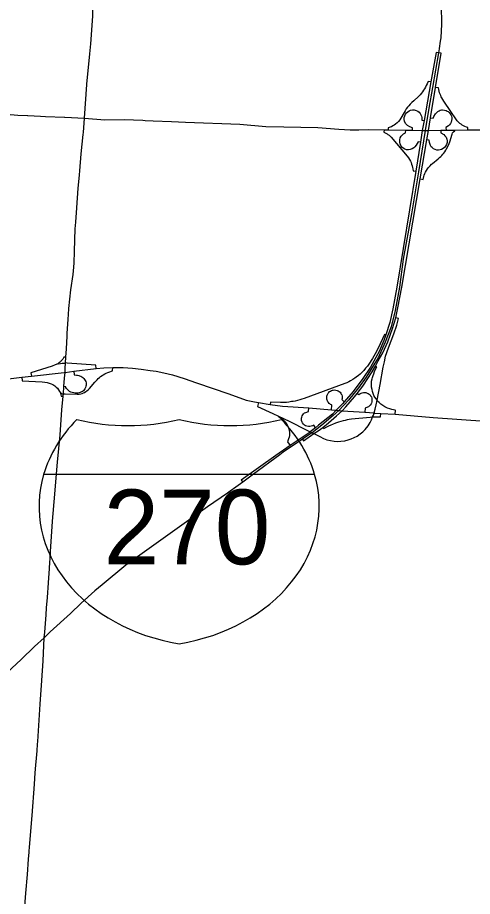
# Model space of a CAD drawing. Extents: x -7.1 to 34, y 0 to 22.
# Drawn here: x 7.196 to 7.759, y 16.034 to 17.122 of the extents above; entities that cross this region are included whole.
import ezdxf

# ---------------------------------------------------------------- set-up
doc = ezdxf.new("R2010")
doc.units = 0
for name, color, linetype in [('GM_X_Interchange_Ramps', 7, 'Continuous'), ('GM_X_Interstate_Route', 7, 'Continuous'), ('GM_X_Interstate_Shield', 7, 'Continuous'), ('GM_X_State_Route', 7, 'Continuous'), ('GM_X_US_Route', 7, 'Continuous')]:
    doc.layers.add(name, color=color, linetype=linetype)

msp = doc.modelspace()

# ---------------------------------------------------------------- linework, layer by layer
at = {"layer": 'GM_X_Interchange_Ramps'}
for points in [[(7.7167, 17.0785), (7.7138, 17.079), (7.7074, 17.0426), (7.699, 16.9948), (7.6968, 16.9823), (7.6944, 16.9677), (7.6886, 16.9318), (7.6653, 16.7884), (7.6603, 16.7615), (7.6566, 16.7446), (7.6515, 16.729), (7.6492, 16.7223), (7.6433, 16.7084), (7.6325, 16.6893), (7.6233, 16.675), (7.6111, 16.6589), (7.6002, 16.646), (7.5986, 16.6441), (7.5903, 16.6358), (7.5856, 16.631), (7.5684, 16.6171), (7.5646, 16.6141), (7.5581, 16.6089), (7.5579, 16.6088), (7.5333, 16.592), (7.5153, 16.5798), (7.4725, 16.5493), (7.4745, 16.5465)], [(7.5485, 16.5999), (7.5498, 16.598), (7.5625, 16.6068), (7.5678, 16.6104), (7.5737, 16.6145), (7.5808, 16.6202), (7.5906, 16.6287), (7.5974, 16.6352), (7.6023, 16.64), (7.6127, 16.6522), (7.6162, 16.6567), (7.6231, 16.6654), (7.6347, 16.6834), (7.6387, 16.6905), (7.6423, 16.697), (7.6478, 16.7069), (7.654, 16.7205), (7.6599, 16.7369), (7.6639, 16.7503), (7.6664, 16.7627), (7.6714, 16.7883), (7.6943, 16.9223), (7.7026, 16.9707), (7.7046, 16.9823), (7.7046, 16.9824), (7.7071, 16.9979), (7.7133, 17.0356), (7.7202, 17.078), (7.7167, 17.0785)], [(7.7074, 17.0426), (7.7041, 17.0431), (7.7028, 17.0401), (7.7018, 17.0379), (7.7007, 17.0359), (7.6997, 17.034), (7.6985, 17.0322), (7.6971, 17.0302), (7.6957, 17.0284), (7.6942, 17.0265), (7.6933, 17.0255), (7.6919, 17.0242), (7.6865, 17.0192), (7.684, 17.0169), (7.6819, 17.0149), (7.68, 17.0128), (7.6785, 17.011), (7.677, 17.0089), (7.6756, 17.0067), (7.6743, 17.0047), (7.6702, 16.9974), (7.6689, 16.9954), (7.6675, 16.9935), (7.6658, 16.9917), (7.6637, 16.9899), (7.662, 16.9887), (7.6605, 16.9879), (7.6588, 16.987), (7.6569, 16.9863), (7.6545, 16.9856), (7.6545, 16.983)], [(7.7534, 16.983), (7.7533, 16.986), (7.7514, 16.9865), (7.7496, 16.9872), (7.7479, 16.988), (7.7463, 16.9889), (7.7448, 16.9899), (7.7434, 16.991), (7.742, 16.9922), (7.7409, 16.9933), (7.74, 16.9944), (7.7234, 17.0188), (7.7221, 17.0207), (7.721, 17.0226), (7.7203, 17.024), (7.7196, 17.0255), (7.7189, 17.0272), (7.7183, 17.029), (7.7177, 17.031), (7.7169, 17.035), (7.7133, 17.0356)], [(7.6847, 16.9825), (7.6848, 16.9855), (7.6814, 16.9868), (7.6785, 16.9884), (7.676, 16.9911), (7.6749, 16.9937), (7.6745, 16.996), (7.6745, 16.9982), (7.6751, 17.0006), (7.6759, 17.0023), (7.6773, 17.0042), (7.6787, 17.0055), (7.6805, 17.0066), (7.6823, 17.0073), (7.6845, 17.0077), (7.6868, 17.0077), (7.6894, 17.007), (7.6911, 17.0061), (7.6928, 17.0048), (7.6942, 17.0032), (7.6952, 17.0016), (7.6958, 16.9999), (7.6961, 16.9984), (7.6964, 16.9952), (7.699, 16.9948)], [(7.7071, 16.9979), (7.7104, 16.9974), (7.7113, 16.9997), (7.7131, 17.003), (7.7142, 17.0043), (7.716, 17.0059), (7.7175, 17.0067), (7.7191, 17.0073), (7.7205, 17.0077), (7.722, 17.0078), (7.7241, 17.0076), (7.7262, 17.0071), (7.7276, 17.0064), (7.7289, 17.0056), (7.7302, 17.0044), (7.7313, 17.003), (7.7321, 17.0017), (7.7328, 17), (7.7332, 16.9983), (7.7333, 16.9966), (7.7331, 16.9948), (7.7325, 16.9927), (7.7316, 16.9909), (7.7304, 16.9892), (7.7292, 16.9881), (7.7261, 16.986), (7.7262, 16.9826)], [(7.6494, 16.9831), (7.6493, 16.9801), (7.6518, 16.979), (7.6532, 16.9782), (7.6543, 16.9775), (7.6556, 16.9766), (7.6569, 16.9754), (7.6583, 16.9739), (7.678, 16.9503), (7.6796, 16.9483), (7.6808, 16.9464), (7.682, 16.9444), (7.6829, 16.9426), (7.6836, 16.9407), (7.6843, 16.9387), (7.6848, 16.9366), (7.6852, 16.9348), (7.6854, 16.9323), (7.6886, 16.9318)], [(7.6944, 16.9677), (7.6916, 16.9682), (7.6891, 16.9639), (7.6877, 16.9622), (7.6862, 16.9607), (7.6841, 16.9594), (7.6819, 16.9586), (7.6796, 16.9583), (7.6774, 16.9585), (7.6751, 16.9593), (7.6732, 16.9604), (7.6715, 16.9618), (7.6703, 16.9635), (7.6693, 16.9657), (7.6688, 16.9679), (7.6689, 16.9707), (7.6695, 16.973), (7.6706, 16.9751), (7.6721, 16.9769), (7.6737, 16.9781), (7.6762, 16.9795), (7.6763, 16.9827)], [(7.6943, 16.9223), (7.6977, 16.9217), (7.6987, 16.9253), (7.6993, 16.9271), (7.7, 16.9288), (7.7009, 16.9307), (7.7021, 16.9328), (7.7034, 16.9349), (7.7046, 16.9365), (7.7064, 16.9385), (7.7084, 16.9404), (7.7094, 16.9413), (7.7164, 16.9473), (7.7181, 16.9487), (7.7196, 16.9501), (7.721, 16.9514), (7.7222, 16.9528), (7.7234, 16.9543), (7.7247, 16.956), (7.7259, 16.9577), (7.7269, 16.9596), (7.7293, 16.9641), (7.7309, 16.9683), (7.7338, 16.9778), (7.7344, 16.9794), (7.7354, 16.9807), (7.7369, 16.9818), (7.7369, 16.9828)], [(7.7197, 16.9825), (7.7198, 16.9793), (7.7233, 16.9775), (7.7249, 16.9758), (7.7263, 16.9738), (7.7271, 16.9715), (7.7274, 16.9695), (7.7274, 16.9674), (7.7267, 16.9648), (7.7256, 16.9627), (7.7242, 16.961), (7.7227, 16.9598), (7.7207, 16.9588), (7.7189, 16.9582), (7.7169, 16.9579), (7.7149, 16.958), (7.7127, 16.9586), (7.7106, 16.9597), (7.709, 16.961), (7.7079, 16.9621), (7.707, 16.9636), (7.7064, 16.965), (7.7058, 16.9674), (7.7054, 16.9703), (7.7026, 16.9707)], [(7.4938, 16.6452), (7.4929, 16.6405), (7.5119, 16.6318), (7.5189, 16.6285), (7.5321, 16.6223), (7.5539, 16.611), (7.5581, 16.6089), (7.5604, 16.6078), (7.5625, 16.6068), (7.5698, 16.6032), (7.5746, 16.6008), (7.5788, 16.5992), (7.583, 16.5981), (7.5877, 16.5974), (7.5923, 16.5971), (7.596, 16.5973), (7.6008, 16.5979), (7.6051, 16.5989), (7.6089, 16.6002), (7.6126, 16.6018), (7.6163, 16.6038), (7.6199, 16.6064), (7.6233, 16.6092), (7.6262, 16.6121), (7.6296, 16.6164), (7.6321, 16.6204), (7.6339, 16.6239), (7.6353, 16.6274), (7.6362, 16.6296), (7.6372, 16.6324), (7.6373, 16.6326), (7.6386, 16.637), (7.6397, 16.6423), (7.6409, 16.6481), (7.6447, 16.6678), (7.6482, 16.689), (7.6498, 16.6959), (7.6514, 16.7026), (7.655, 16.7131), (7.6617, 16.7303), (7.6653, 16.7412), (7.6675, 16.7493), (7.6639, 16.7503)], [(7.6515, 16.729), (7.65, 16.7295), (7.6447, 16.7181), (7.6399, 16.7086), (7.635, 16.6997), (7.6304, 16.6927), (7.6289, 16.6905), (7.6266, 16.6877), (7.6244, 16.6851), (7.6221, 16.6827), (7.6198, 16.6806), (7.6178, 16.6789), (7.6151, 16.6768), (7.6131, 16.6753), (7.6107, 16.6738), (7.6079, 16.6721), (7.6058, 16.671), (7.6034, 16.6698), (7.601, 16.6688), (7.5507, 16.6502), (7.5478, 16.6493), (7.5453, 16.6486), (7.5421, 16.6478), (7.5392, 16.6472), (7.5368, 16.6467), (7.5349, 16.6464), (7.5314, 16.6458), (7.5285, 16.6455), (7.5213, 16.6452), (7.5088, 16.6458), (7.5084, 16.6427)], [(7.2555, 16.7014), (7.2531, 16.7016), (7.2521, 16.7), (7.2515, 16.6991), (7.2509, 16.6983), (7.2502, 16.6975), (7.2494, 16.6966), (7.2487, 16.6959), (7.2477, 16.695), (7.2469, 16.6944), (7.2456, 16.6934), (7.2422, 16.6918), (7.2384, 16.6904), (7.2122, 16.6823), (7.2127, 16.6781)], [(7.255, 16.6935), (7.2535, 16.6936), (7.2525, 16.6937), (7.2508, 16.6936), (7.2486, 16.6931), (7.2461, 16.6927), (7.2456, 16.6934)], [(7.2523, 16.6562), (7.2547, 16.6561), (7.2694, 16.6555), (7.2721, 16.6558), (7.2738, 16.6561), (7.2758, 16.6567), (7.2771, 16.6573), (7.2785, 16.6579), (7.2801, 16.6588), (7.2815, 16.6598), (7.2829, 16.661), (7.2845, 16.6626), (7.2914, 16.6704), (7.293, 16.6723), (7.2941, 16.6735), (7.2956, 16.6751), (7.297, 16.6763), (7.2985, 16.6775), (7.3002, 16.6788), (7.3017, 16.6797), (7.3035, 16.6808), (7.3053, 16.6816), (7.3072, 16.6825), (7.3088, 16.6831), (7.3133, 16.6845), (7.3134, 16.6886)], [(7.293, 16.6874), (7.2926, 16.6914), (7.2571, 16.6942), (7.2551, 16.6944)], [(7.6632, 16.6307), (7.6636, 16.6356), (7.6633, 16.6357), (7.661, 16.6361), (7.6591, 16.6366), (7.6566, 16.6374), (7.6537, 16.6384), (7.6503, 16.64), (7.6479, 16.6415), (7.6455, 16.6433), (7.6433, 16.6452), (7.6419, 16.6467), (7.6409, 16.6481), (7.6395, 16.6499), (7.6382, 16.6519), (7.637, 16.6542), (7.6359, 16.6567), (7.6352, 16.6589), (7.6346, 16.6613), (7.6341, 16.6645), (7.6339, 16.6672), (7.6339, 16.6694), (7.6341, 16.6717), (7.6346, 16.6745), (7.6351, 16.6765), (7.6359, 16.6789), (7.6366, 16.681), (7.6377, 16.6837), (7.639, 16.6865), (7.6405, 16.6895), (7.6387, 16.6905)], [(7.2652, 16.684), (7.2657, 16.6796), (7.2684, 16.6793), (7.2699, 16.679), (7.2714, 16.6787), (7.2725, 16.6784), (7.2739, 16.6778), (7.2753, 16.677), (7.2764, 16.6762), (7.2777, 16.675), (7.2787, 16.6738), (7.2795, 16.6725), (7.28, 16.6713), (7.2804, 16.6699), (7.2805, 16.6684), (7.2805, 16.6668), (7.2802, 16.6654), (7.2798, 16.664), (7.279, 16.6624), (7.278, 16.6609), (7.2773, 16.66), (7.2761, 16.6591), (7.275, 16.6585), (7.2733, 16.6578), (7.2718, 16.6573), (7.2703, 16.657), (7.2685, 16.6569), (7.2668, 16.6569), (7.2651, 16.6572), (7.2633, 16.6576), (7.2617, 16.6583), (7.2601, 16.6591), (7.2586, 16.6601), (7.2573, 16.6615), (7.2564, 16.6626), (7.2556, 16.664), (7.2552, 16.6649), (7.2531, 16.6651)], [(7.2009, 16.6766), (7.2012, 16.6721), (7.2259, 16.6709), (7.2292, 16.6706), (7.2322, 16.6702), (7.2349, 16.6695), (7.2372, 16.6685), (7.2395, 16.6675), (7.2417, 16.666), (7.2434, 16.6645), (7.245, 16.663), (7.2465, 16.6611), (7.2477, 16.6591), (7.2487, 16.6573), (7.2489, 16.6567), (7.2491, 16.6556), (7.2493, 16.6547), (7.2497, 16.6533), (7.2521, 16.6532)], [(7.2487, 16.6573), (7.2491, 16.6574), (7.2499, 16.6566), (7.2508, 16.6562), (7.2523, 16.6562)], [(7.5844, 16.6363), (7.5848, 16.6422), (7.5844, 16.6423), (7.5833, 16.643), (7.5825, 16.6435), (7.5815, 16.6443), (7.5807, 16.6452), (7.5799, 16.6463), (7.5793, 16.6474), (7.579, 16.6483), (7.5786, 16.6495), (7.5785, 16.6506), (7.5785, 16.6521), (7.5787, 16.6533), (7.579, 16.6546), (7.5797, 16.656), (7.5804, 16.6571), (7.5811, 16.6579), (7.5821, 16.6588), (7.5831, 16.6595), (7.5842, 16.6601), (7.5855, 16.6605), (7.5866, 16.6608), (7.5881, 16.6609), (7.5898, 16.6607), (7.5913, 16.6603), (7.5925, 16.6598), (7.5938, 16.6589), (7.5949, 16.658), (7.5958, 16.6569), (7.5965, 16.6558), (7.597, 16.6547), (7.5974, 16.6533), (7.5976, 16.6519), (7.5975, 16.6505), (7.5973, 16.6489), (7.6002, 16.646)], [(7.6162, 16.6567), (7.6182, 16.6552), (7.6195, 16.6562), (7.6212, 16.6571), (7.6225, 16.6575), (7.6239, 16.6578), (7.6253, 16.6578), (7.6268, 16.6576), (7.6286, 16.6571), (7.6298, 16.6565), (7.631, 16.6557), (7.6321, 16.6547), (7.6328, 16.6537), (7.6337, 16.6522), (7.6342, 16.6507), (7.6345, 16.6491), (7.6345, 16.6477), (7.6343, 16.646), (7.6339, 16.6447), (7.6334, 16.6436), (7.6324, 16.6422), (7.6314, 16.6411), (7.6301, 16.6401), (7.6289, 16.6394), (7.6259, 16.6384), (7.6255, 16.6332)], [(7.5646, 16.6141), (7.5624, 16.6171), (7.5609, 16.6166), (7.5591, 16.6161), (7.5574, 16.6158), (7.5557, 16.6157), (7.5539, 16.616), (7.5522, 16.6166), (7.5509, 16.6174), (7.5495, 16.6187), (7.5485, 16.62), (7.5479, 16.6211), (7.5473, 16.623), (7.5472, 16.6244), (7.5472, 16.6261), (7.5475, 16.6273), (7.5481, 16.6288), (7.5488, 16.6301), (7.5498, 16.6313), (7.5511, 16.6324), (7.5524, 16.6331), (7.5559, 16.6344), (7.5561, 16.6387)], [(7.5189, 16.6285), (7.5186, 16.6278), (7.5204, 16.6269), (7.5225, 16.6256), (7.5246, 16.624), (7.5266, 16.622), (7.5281, 16.6201), (7.5292, 16.6185), (7.53, 16.6169), (7.5309, 16.6148), (7.5316, 16.6126), (7.532, 16.6105), (7.5322, 16.6085), (7.5323, 16.6068), (7.5322, 16.6046), (7.5319, 16.6026), (7.5312, 16.6002), (7.5299, 16.5966), (7.5333, 16.592)], [(7.5737, 16.6145), (7.5748, 16.6131), (7.5787, 16.6152), (7.581, 16.6164), (7.5838, 16.6176), (7.5861, 16.6186), (7.5898, 16.6201), (7.5934, 16.6213), (7.5963, 16.6222), (7.5991, 16.623), (7.6016, 16.6236), (7.6043, 16.6242), (7.6062, 16.6246), (7.6093, 16.6251), (7.6322, 16.6272), (7.6353, 16.6274), (7.6383, 16.6275), (7.6448, 16.6277), (7.6452, 16.6277), (7.6455, 16.6318)]]:
    msp.add_lwpolyline(points, dxfattribs=at)
at = {"layer": 'GM_X_Interstate_Route'}
for points in [[(7.6998, 17.226), (7.7006, 17.2243), (7.7068, 17.207), (7.7113, 17.1918), (7.7136, 17.1821), (7.7158, 17.1731), (7.7172, 17.1646), (7.7189, 17.152), (7.7203, 17.1369), (7.7207, 17.1139), (7.7196, 17.0969), (7.719, 17.0931)], [(7.719, 17.0931), (7.7176, 17.0837), (7.7176, 17.0834)], [(7.7176, 17.0834), (7.7167, 17.0785)], [(7.7167, 17.0785), (7.7095, 17.0354), (7.705, 17.0099), (7.7003, 16.9823)], [(7.7003, 16.9823), (7.692, 16.9311), (7.6835, 16.879), (7.673, 16.8228), (7.6686, 16.7884), (7.6633, 16.7592), (7.6581, 16.739), (7.6508, 16.7201), (7.642, 16.7008), (7.6273, 16.6767), (7.618, 16.6635), (7.6055, 16.6484), (7.5934, 16.6355)], [(7.2533, 16.6826), (7.2544, 16.6827), (7.2652, 16.684), (7.293, 16.6874), (7.3024, 16.6882), (7.3134, 16.6886), (7.3264, 16.6885), (7.338, 16.6879), (7.3485, 16.6866), (7.36, 16.6851), (7.3672, 16.684), (7.3768, 16.6821), (7.3873, 16.6796), (7.4018, 16.6752), (7.4171, 16.6698), (7.4572, 16.6561), (7.4788, 16.6484), (7.489, 16.6462), (7.4913, 16.6457)], [(7.154, 16.671), (7.2009, 16.6766), (7.2127, 16.6781), (7.2533, 16.6826)], [(7.4913, 16.6457), (7.4938, 16.6452), (7.5084, 16.6427), (7.5235, 16.641), (7.5561, 16.6387)], [(7.5934, 16.6355), (7.5864, 16.6294), (7.5724, 16.6172), (7.5604, 16.6078), (7.5602, 16.6077), (7.5485, 16.5999)], [(7.5561, 16.6387), (7.5844, 16.6363), (7.5903, 16.6358), (7.5934, 16.6355)], [(7.5934, 16.6355), (7.5974, 16.6352), (7.6255, 16.6332), (7.6372, 16.6324), (7.6374, 16.6323), (7.6455, 16.6318)], [(7.6455, 16.6318), (7.6455, 16.6318), (7.6632, 16.6307)], [(7.6632, 16.6307), (7.7102, 16.6268), (7.8097, 16.6198), (7.8437, 16.6166), (7.8459, 16.6165), (7.8758, 16.6135), (7.8877, 16.6127)], [(7.5485, 16.5999), (7.5485, 16.5999), (7.5245, 16.5838), (7.5202, 16.5806)], [(7.5202, 16.5806), (7.4877, 16.5564), (7.4745, 16.5465)], [(7.4745, 16.5465), (7.4658, 16.5405)], [(7.4658, 16.5405), (7.459, 16.5357), (7.4554, 16.5332)], [(7.4554, 16.5332), (7.431, 16.5162), (7.4134, 16.5039), (7.3298, 16.4438), (7.3002, 16.4196), (7.2914, 16.4119), (7.2745, 16.3967), (7.2611, 16.384), (7.236, 16.3611), (7.2286, 16.3538)], [(7.2286, 16.3538), (7.2168, 16.343), (7.2001, 16.3272)], [(7.2001, 16.3272), (7.177, 16.3054), (7.1556, 16.2849), (7.1388, 16.269), (7.1201, 16.2493), (7.1066, 16.236), (7.0954, 16.2239), (7.0917, 16.2195)]]:
    msp.add_lwpolyline(points, dxfattribs=at)
at = {"layer": 'GM_X_Interstate_Shield'}
msp.add_line((7.5635, 16.5563), (7.2279, 16.5563), dxfattribs=at)
msp.add_line((7.5635, 16.5563), (7.2279, 16.5563), dxfattribs=at)
for centre, start_param, end_param in [((7.4391, 16.5166), 2.47259, 2.911027), ((7.3323, 16.7902), 4.415841, 5.008937), ((7.4591, 16.7902), 4.415841, 5.008937), ((7.3523, 16.5166), 0.230566, 0.669003), ((7.4391, 16.5166), 2.911027, 4.511031), ((7.3523, 16.5166), 4.913747, 6.513751)]:
    msp.add_ellipse(centre, major_axis=(0.2169, 0), ratio=0.8, start_param=start_param, end_param=end_param, dxfattribs=at)
at = {"layer": 'GM_X_State_Route'}
for points in [[(7.2862, 17.0897), (7.2887, 17.124), (7.2887, 17.1327), (7.2888, 17.1335)], [(7.2786, 16.9976), (7.2816, 17.0394), (7.2816, 17.0398), (7.2853, 17.0771), (7.2862, 17.0897)], [(7.2722, 16.9273), (7.2727, 16.9324), (7.2745, 16.9532), (7.277, 16.9774), (7.2772, 16.9796), (7.2786, 16.9976)], [(7.2663, 16.8326), (7.2671, 16.8604), (7.2677, 16.8688), (7.269, 16.8864), (7.2708, 16.911), (7.2722, 16.9268), (7.2722, 16.9271), (7.2722, 16.9273)], [(7.265, 16.8085), (7.2659, 16.818), (7.2663, 16.8326)], [(7.257, 16.7277), (7.2571, 16.7294), (7.2572, 16.7313), (7.2583, 16.7481), (7.2592, 16.7615), (7.2592, 16.7618), (7.2614, 16.7849), (7.2646, 16.8041), (7.265, 16.8085)], [(7.2547, 16.6883), (7.255, 16.6935), (7.2551, 16.6944), (7.2555, 16.7014), (7.2561, 16.7117), (7.257, 16.7277)], [(7.2539, 16.6754), (7.2544, 16.6827), (7.2547, 16.6883)], [(7.245, 16.5714), (7.2483, 16.6052), (7.2505, 16.6363), (7.2505, 16.6364), (7.2521, 16.6532), (7.2523, 16.6562), (7.2531, 16.6651), (7.2539, 16.6754)], [(7.2359, 16.4518), (7.2365, 16.4609), (7.239, 16.4981), (7.239, 16.4985), (7.2417, 16.5319), (7.2417, 16.5322), (7.245, 16.5714)], [(7.235, 16.4399), (7.2356, 16.4474), (7.2358, 16.4518), (7.2359, 16.4518)], [(7.2325, 16.404), (7.2325, 16.404), (7.2338, 16.4218), (7.235, 16.4398), (7.235, 16.4399)], [(7.2309, 16.3824), (7.2309, 16.3825), (7.2316, 16.3909), (7.2325, 16.404)], [(7.2292, 16.3609), (7.2292, 16.3609), (7.2309, 16.3824)], [(7.2272, 16.3253), (7.2286, 16.3538), (7.2292, 16.3609)], [(7.2257, 16.301), (7.2272, 16.3253)], [(7.2238, 16.2718), (7.2257, 16.301)], [(7.2208, 16.2256), (7.2238, 16.2718)], [(7.2103, 16.0945), (7.2136, 16.1339), (7.2167, 16.1725), (7.2176, 16.1867), (7.2184, 16.196), (7.219, 16.205), (7.2198, 16.2139), (7.2205, 16.2222), (7.2208, 16.2256)], [(7.2092, 16.0799), (7.2098, 16.0884), (7.2099, 16.0897)], [(7.2099, 16.0897), (7.2103, 16.0945)], [(7.1972, 15.928), (7.1989, 15.9466), (7.2059, 16.0375), (7.2079, 16.0605), (7.2092, 16.0799)]]:
    msp.add_lwpolyline(points, dxfattribs=at)
at = {"layer": 'GM_X_US_Route'}
for points in [[(6.9209, 17.0136), (6.9299, 17.0132), (6.9604, 17.0118), (6.9694, 17.0112), (6.9704, 17.0111), (7.0168, 17.0089), (7.0532, 17.0072), (7.0535, 17.0072), (7.0746, 17.0065), (7.1238, 17.0049), (7.1246, 17.0048), (7.1552, 17.0034), (7.1689, 17.0029), (7.1821, 17.0023), (7.1958, 17.0013), (7.2079, 17.0007), (7.2084, 17.0007), (7.2239, 17), (7.2302, 16.9997), (7.2536, 16.9986), (7.2543, 16.9986), (7.2786, 16.9976)], [(7.2786, 16.9976), (7.3038, 16.9953), (7.3277, 16.996), (7.3509, 16.9949), (7.3536, 16.9948)], [(7.3536, 16.9948), (7.3636, 16.9943)], [(7.3636, 16.9943), (7.3861, 16.9934)], [(7.3861, 16.9934), (7.4036, 16.9927), (7.4709, 16.9899), (7.5031, 16.9871), (7.5252, 16.9867), (7.5676, 16.986), (7.5934, 16.9841)], [(7.5934, 16.9841), (7.6076, 16.983), (7.6181, 16.9832)], [(7.6181, 16.9832), (7.6305, 16.9833), (7.6494, 16.9831), (7.6545, 16.983), (7.6763, 16.9827), (7.6847, 16.9825), (7.6968, 16.9823), (7.7003, 16.9823)], [(7.7003, 16.9823), (7.7046, 16.9823), (7.7197, 16.9825), (7.7262, 16.9826), (7.7369, 16.9828), (7.7534, 16.983), (7.7706, 16.9832)]]:
    msp.add_lwpolyline(points, dxfattribs=at)

# ---------------------------------------------------------------- texts
at = {"layer": 'GM_X_Interstate_Shield'}
msp.add_text('270', height=0.09255, dxfattribs=at).set_placement((7.3022, 16.4449))

doc.saveas('drawing.dxf')
